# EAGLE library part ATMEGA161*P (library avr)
MICROCONTROLLER 16 Kbytes FLASH, 512 bytes EEPROM 1 Kbytes SRAM dual UART hardware multiplier
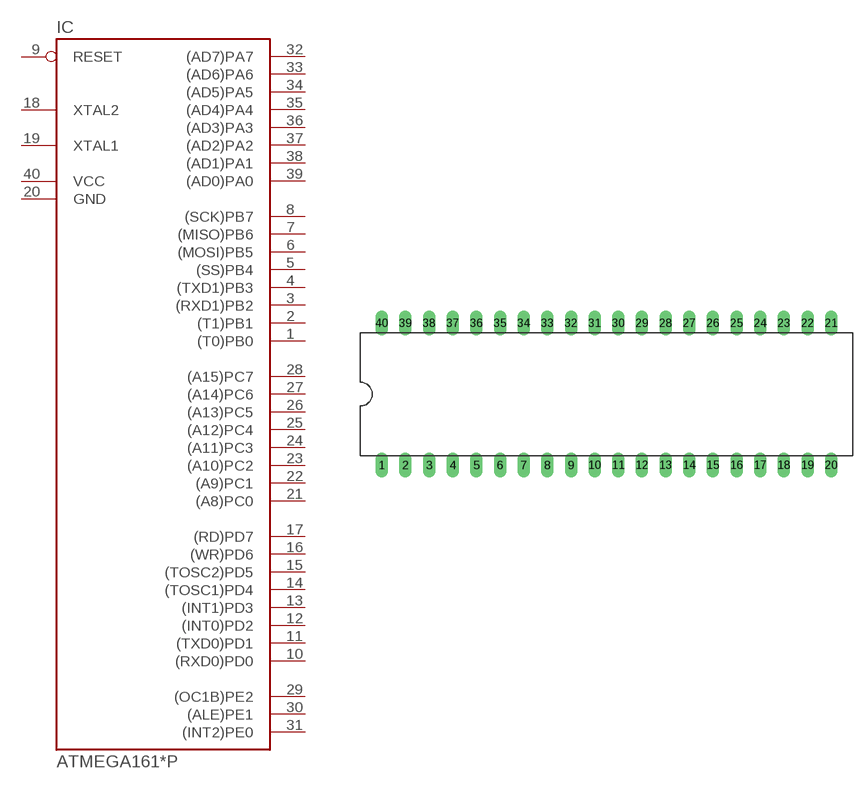
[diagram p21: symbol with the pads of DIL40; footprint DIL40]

Designator prefix IC

## ATMEGA161-8P, ATMEGA161L-4P  [DIL40]
1  (T0)PB0
2  (T1)PB1
3  (RXD1)PB2
4  (TXD1)PB3
5  (SS)PB4
6  (MOSI)PB5
7  (MISO)PB6
8  (SCK)PB7
9  RESET  in
10  (RXD0)PD0
11  (TXD0)PD1
12  (INT0)PD2
13  (INT1)PD3
14  (TOSC1)PD4
15  (TOSC2)PD5
16  (WR)PD6
17  (RD)PD7
18  XTAL2  in
19  XTAL1  in
20  GND  pwr
21  (A8)PC0
22  (A9)PC1
23  (A10)PC2
24  (A11)PC3
25  (A12)PC4
26  (A13)PC5
27  (A14)PC6
28  (A15)PC7
29  (OC1B)PE2
30  (ALE)PE1
31  (INT2)PE0
32  (AD7)PA7
33  (AD6)PA6
34  (AD5)PA5
35  (AD4)PA4
36  (AD3)PA3
37  (AD2)PA2
38  (AD1)PA1
39  (AD0)PA0
40  VCC  pwr

## Footprint DIL40 (pad centres in mm)
Dual In Line
drill 0.813 long: 1 -24.13,-7.62; 2 -21.59,-7.62; 3 -19.05,-7.62; 4 -16.51,-7.62; 5 -13.97,-7.62; 6 -11.43,-7.62; 7 -8.89,-7.62; 8 -6.35,-7.62; 9 -3.81,-7.62; 10 -1.27,-7.62; 11 1.27,-7.62; 12 3.81,-7.62; 13 6.35,-7.62; 14 8.89,-7.62; 15 11.43,-7.62; 16 13.97,-7.62; 17 16.51,-7.62; 18 19.05,-7.62; 19 21.59,-7.62; 20 24.13,-7.62; 21 24.13,7.62; 22 21.59,7.62; 23 19.05,7.62; 24 16.51,7.62; 25 13.97,7.62; 26 11.43,7.62; 27 8.89,7.62; 28 6.35,7.62; 29 3.81,7.62; 30 1.27,7.62; 31 -1.27,7.62; 32 -3.81,7.62; 33 -6.35,7.62; 34 -8.89,7.62; 35 -11.43,7.62; 36 -13.97,7.62; 37 -16.51,7.62; 38 -19.05,7.62; 39 -21.59,7.62; 40 -24.13,7.62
